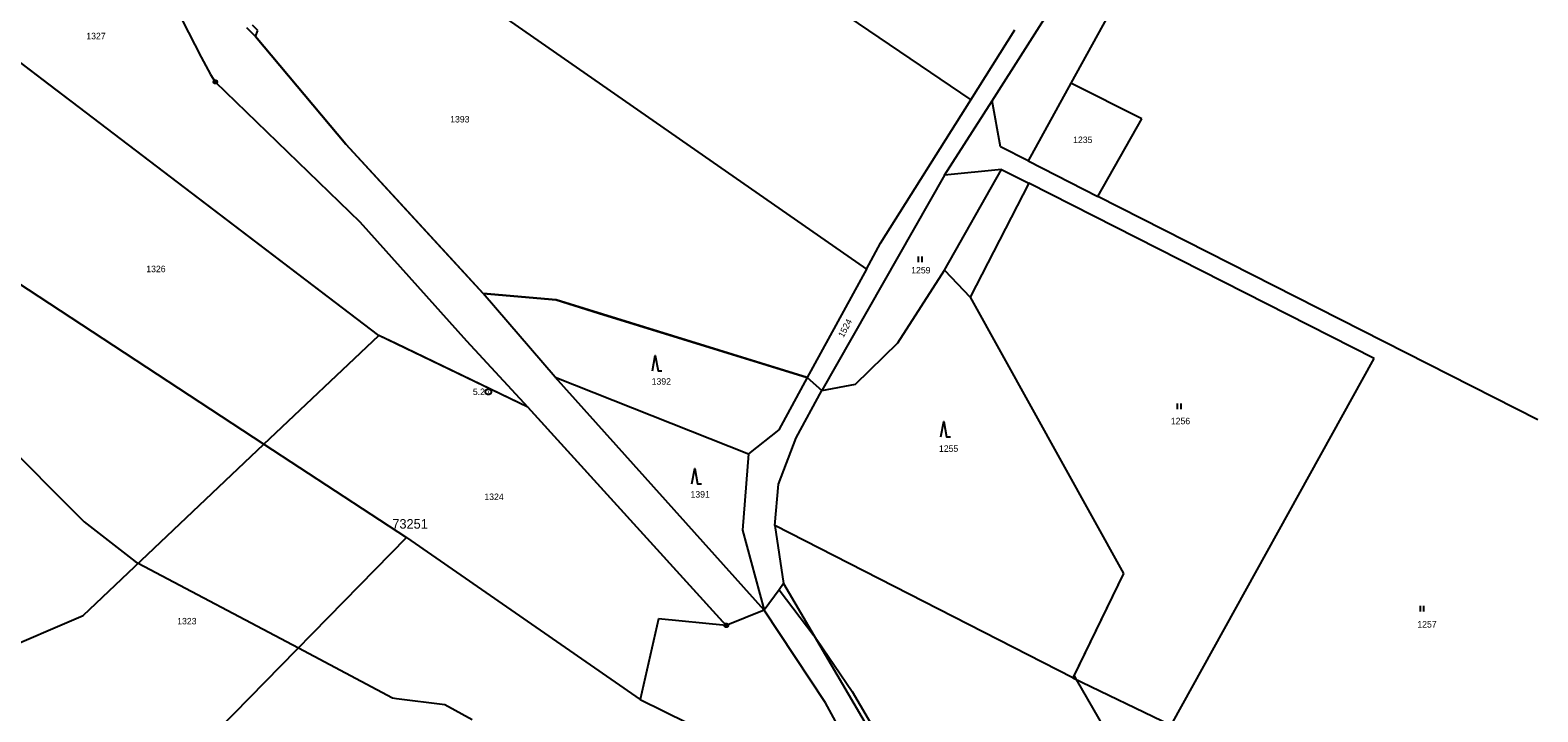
# Model space of a CAD drawing. Extents: x -792913 to -792113, y -1112764 to -1111548.
# Drawn here: x -792595.9 to -792201, y -1112340 to -1112161.5 of the extents above; entities that cross this region are included whole.
import ezdxf

# ---------------------------------------------------------------- set-up
doc = ezdxf.new("R2010")
doc.units = 0
for name, color, linetype in [('Vrstva 1', 7, 'Continuous'), ('Vrstva 11', 7, 'Continuous'), ('Vrstva 2', 7, 'Continuous'), ('Vrstva 3', 7, 'Continuous'), ('Vrstva 8', 7, 'Continuous')]:
    doc.layers.add(name, color=color, linetype=linetype)

msp = doc.modelspace()

# ---------------------------------------------------------------- linework, layer by layer
at = {"layer": 'Vrstva 1'}
for p, q in [((-792273.08, -1112083.84), (-792323.32, -1112175.38)), ((-792463.83, -1112102.18), (-792349.52, -1112179.73)), ((-792343.98, -1112180.01), (-792304.62, -1112118.38)), ((-792567.46, -1112136.79), (-792551.14, -1112168.59)), ((-792475.03, -1112155.83), (-792376.89, -1112224.11)), ((-792536.31, -1112161.61), (-792537.7, -1112160.18)), ((-792536.88, -1112163.17), (-792536.31, -1112161.61)), ((-792349.52, -1112179.73), (-792337.97, -1112161.4)), ((-792513.25, -1112191.36), (-792536.88, -1112163.17)), ((-792504.64, -1112241.47), (-792602.02, -1112167.3)), ((-792551.14, -1112168.59), (-792548.73, -1112173.1)), ((-792548.73, -1112173.1), (-792547.43, -1112175.05)), ((-792547.43, -1112175.05), (-792509.59, -1112211.73)), ((-792323.32, -1112175.38), (-792334.54, -1112195.75)), ((-792304.73, -1112184.75), (-792323.32, -1112175.38)), ((-792373.16, -1112217.27), (-792349.52, -1112179.73)), ((-792356.43, -1112199.49), (-792343.98, -1112180.01)), ((-792341.75, -1112192.1), (-792343.98, -1112180.01)), ((-792316.25, -1112205.03), (-792304.73, -1112184.75)), ((-792477.24, -1112230.47), (-792513.25, -1112191.36)), ((-792341.75, -1112192.1), (-792341.75, -1112192.1)), ((-792334.54, -1112195.75), (-792341.75, -1112192.1)), ((-792356.45, -1112224.4), (-792341.48, -1112197.97)), ((-792341.48, -1112197.97), (-792356.43, -1112199.49)), ((-792341.48, -1112197.97), (-792334.34, -1112201.6)), ((-792334.54, -1112195.75), (-792316.25, -1112205.03)), ((-792356.43, -1112199.49), (-792388.54, -1112255.91)), ((-792334.34, -1112201.6), (-792349.73, -1112231.42)), ((-792243.89, -1112247.46), (-792334.34, -1112201.6)), ((-792201.02, -1112263.52), (-792316.25, -1112205.03)), ((-792509.59, -1112211.73), (-792481.67, -1112242.9)), ((-792376.89, -1112224.11), (-792373.16, -1112217.27)), ((-792610.82, -1112220.07), (-792534.68, -1112269.92)), ((-792376.89, -1112224.11), (-792392.37, -1112252.5)), ((-792368.64, -1112243.39), (-792356.45, -1112224.4)), ((-792458.43, -1112252.34), (-792477.24, -1112230.47)), ((-792458.19, -1112232.15), (-792477.24, -1112230.47)), ((-792392.37, -1112252.5), (-792458.19, -1112232.15)), ((-792349.73, -1112231.42), (-792309.59, -1112303.83)), ((-792534.68, -1112269.92), (-792504.64, -1112241.47)), ((-792465.6, -1112260.2), (-792504.64, -1112241.47)), ((-792481.67, -1112242.9), (-792465.6, -1112260.2)), ((-792379.75, -1112254.24), (-792368.64, -1112243.39)), ((-792297.07, -1112343.48), (-792243.89, -1112247.46)), ((-792243.89, -1112247.46), (-792243.89, -1112247.46)), ((-792458.43, -1112252.34), (-792407.81, -1112272.49)), ((-792403.69, -1112313.37), (-792458.43, -1112252.34)), ((-792392.37, -1112252.5), (-792399.85, -1112266.21)), ((-792395.3, -1112268.31), (-792388.54, -1112255.91)), ((-792388.54, -1112255.91), (-792379.75, -1112254.24)), ((-792465.6, -1112260.2), (-792413.58, -1112317.39)), ((-792399.85, -1112266.21), (-792407.81, -1112272.49)), ((-792399.9, -1112280.4), (-792395.3, -1112268.31)), ((-792582.04, -1112314.76), (-792534.68, -1112269.92)), ((-792534.68, -1112269.92), (-792497.31, -1112294.38)), ((-792407.81, -1112272.49), (-792409.31, -1112292.45)), ((-792400.87, -1112291.27), (-792399.9, -1112280.4)), ((-792409.31, -1112292.45), (-792403.69, -1112313.37)), ((-792322.81, -1112331.08), (-792400.87, -1112291.27)), ((-792400.87, -1112291.27), (-792398.63, -1112306.46)), ((-792497.31, -1112294.38), (-792562.85, -1112361.21)), ((-792497.31, -1112294.38), (-792436.12, -1112336.84)), ((-792309.59, -1112303.83), (-792322.81, -1112331.08)), ((-792398.63, -1112306.46), (-792371.86, -1112351.99)), ((-792627.65, -1112334.38), (-792582.04, -1112314.76)), ((-792431.33, -1112315.63), (-792436.12, -1112336.84)), ((-792413.58, -1112317.39), (-792431.33, -1112315.63)), ((-792387.56, -1112337.7), (-792403.69, -1112313.37)), ((-792322.81, -1112331.08), (-792297.07, -1112343.48)), ((-792436.12, -1112336.84), (-792391.37, -1112358.8)), ((-792374.42, -1112361.83), (-792387.56, -1112337.7))]:
    msp.add_line(p, q, dxfattribs=at)
at = {"layer": 'Vrstva 11'}
for p, q in [((-792539.26, -1112160.8), (-792536.88, -1112163.17)), ((-792536.88, -1112163.17), (-792513.25, -1112191.36)), ((-792589.1, -1112177.14), (-792602.02, -1112167.3)), ((-792585.16, -1112180.14), (-792589.1, -1112177.14)), ((-792529.86, -1112222.25), (-792585.16, -1112180.14)), ((-792513.25, -1112191.36), (-792500, -1112205.74)), ((-792500, -1112205.74), (-792481.03, -1112226.33)), ((-792504.64, -1112241.47), (-792529.86, -1112222.25)), ((-792368.64, -1112243.39), (-792356.45, -1112224.4)), ((-792356.45, -1112224.4), (-792349.73, -1112231.42)), ((-792481.03, -1112226.33), (-792477.24, -1112230.47)), ((-792477.24, -1112230.47), (-792458.19, -1112232.15)), ((-792458.19, -1112232.15), (-792447.06, -1112235.59)), ((-792349.73, -1112231.42), (-792309.59, -1112303.83)), ((-792447.06, -1112235.59), (-792392.37, -1112252.5)), ((-792500, -1112243.69), (-792504.64, -1112241.47)), ((-792465.6, -1112260.2), (-792500, -1112243.69)), ((-792379.75, -1112254.24), (-792368.64, -1112243.39)), ((-792392.37, -1112252.5), (-792388.54, -1112255.91)), ((-792615.88, -1112256.1), (-792581.75, -1112290.24)), ((-792388.54, -1112255.91), (-792379.75, -1112254.24)), ((-792413.58, -1112317.39), (-792465.6, -1112260.2)), ((-792581.75, -1112290.24), (-792568.38, -1112300.67)), ((-792400.87, -1112291.27), (-792398.63, -1112306.46)), ((-792322.81, -1112331.08), (-792400.87, -1112291.27)), ((-792568.38, -1112300.67), (-792567.6, -1112301.09)), ((-792567.6, -1112301.09), (-792525.68, -1112323.3)), ((-792309.59, -1112303.83), (-792322.49, -1112330.43)), ((-792399.78, -1112308.04), (-792403.69, -1112313.37)), ((-792398.63, -1112306.46), (-792399.78, -1112308.04)), ((-792399.78, -1112308.04), (-792390.62, -1112320.08)), ((-792403.69, -1112313.37), (-792413.58, -1112317.39)), ((-792390.62, -1112320.08), (-792389.83, -1112321.12)), ((-792525.68, -1112323.3), (-792501.04, -1112336.36)), ((-792389.83, -1112321.12), (-792380.59, -1112334.73)), ((-792322.49, -1112330.43), (-792322.81, -1112331.08)), ((-792321.85, -1112331.54), (-792322.49, -1112330.43)), ((-792314.59, -1112344.12), (-792321.85, -1112331.54)), ((-792501.04, -1112336.36), (-792500, -1112336.5)), ((-792500, -1112336.5), (-792487.32, -1112338.15)), ((-792380.59, -1112334.73), (-792363.82, -1112363.21)), ((-792487.32, -1112338.15), (-792480.14, -1112342.01))]:
    msp.add_line(p, q, dxfattribs=at)
at = {"layer": 'Vrstva 3'}
for p, q in [((-792363.3, -1112220.74), (-792363.3, -1112222.24)), ((-792362.3, -1112222.24), (-792362.3, -1112220.74)), ((-792295.47, -1112259.29), (-792295.47, -1112260.79)), ((-792294.47, -1112260.79), (-792294.47, -1112259.29)), ((-792231.84, -1112312.24), (-792231.84, -1112313.74)), ((-792230.84, -1112313.74), (-792230.84, -1112312.24))]:
    msp.add_line(p, q, dxfattribs=at)
for points in [[(-792432.95, -1112250.71), (-792432.2, -1112246.71), (-792431.45, -1112250.71), (-792430.45, -1112250.71)], [(-792357.38, -1112268), (-792356.63, -1112264), (-792355.88, -1112268), (-792354.88, -1112268)], [(-792422.61, -1112280.34), (-792421.86, -1112276.34), (-792421.11, -1112280.34), (-792420.11, -1112280.34)]]:
    msp.add_lwpolyline(points, dxfattribs=at)
at = {"layer": 'Vrstva 8'}
for p, q in [((-792547.55, -1112175.05), (-792547.31, -1112175.05)), ((-792475.96, -1112256.21), (-792475.86, -1112256.21)), ((-792413.7, -1112317.39), (-792413.46, -1112317.39))]:
    msp.add_line(p, q, dxfattribs=at)
for points in [[(-792547.28, -1112174.57), (-792547.03, -1112174.75), (-792546.93, -1112175.04), (-792547.03, -1112175.33), (-792547.28, -1112175.51), (-792547.59, -1112175.51), (-792547.84, -1112175.33), (-792547.94, -1112175.04), (-792547.84, -1112174.75), (-792547.59, -1112174.57)], [(-792475.72, -1112255.49), (-792475.38, -1112255.68), (-792475.19, -1112256.02), (-792475.19, -1112256.41), (-792475.38, -1112256.75), (-792475.72, -1112256.94), (-792476.11, -1112256.94), (-792476.45, -1112256.75), (-792476.64, -1112256.41), (-792476.64, -1112256.02), (-792476.45, -1112255.68), (-792476.11, -1112255.49)], [(-792413.43, -1112316.91), (-792413.18, -1112317.09), (-792413.08, -1112317.38), (-792413.18, -1112317.67), (-792413.43, -1112317.85), (-792413.74, -1112317.85), (-792413.99, -1112317.67), (-792414.09, -1112317.38), (-792413.99, -1112317.09), (-792413.74, -1112316.91)]]:
    msp.add_lwpolyline(points, close=True, dxfattribs=at)

# ---------------------------------------------------------------- texts
at = {"layer": 'Vrstva 11'}
msp.add_text('73251', height=2.5, dxfattribs=at).set_placement((-792501.061, -1112292.06))
at = {"layer": 'Vrstva 2'}
for s, p in [('1327', (-792581.217, -1112163.9)), ('1393', (-792485.907, -1112185.68)), ('1235', (-792322.737, -1112191.07)), ('1326', (-792565.507, -1112224.89)), ('1259', (-792365.157, -1112225.22)), ('1392', (-792433.137, -1112254.35)), ('1256', (-792297.147, -1112264.72)), ('1255', (-792357.887, -1112271.94)), ('1324', (-792476.957, -1112284.56)), ('1391', (-792422.957, -1112283.92)), ('1323', (-792557.407, -1112317.13)), ('1257', (-792232.587, -1112317.96))]:
    msp.add_text(s, height=1.7, dxfattribs=at).set_placement(p)
msp.add_text('1524', height=1.7, rotation=62.05133, dxfattribs=at).set_placement((-792382.906, -1112242.173))
at = {"layer": 'Vrstva 8'}
msp.add_text('5.2', height=1.7, dxfattribs=at).set_placement((-792479.972, -1112257.06))

doc.saveas('drawing.dxf')
